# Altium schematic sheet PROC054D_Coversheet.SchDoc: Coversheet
size 558 x 431 mm; Date: Not shown in title block; ApprovedBy: Not shown in title block; CheckedBy: Not shown in title block; Author: Not shown in title block; CompanyName: Not shown in title block; DrawnBy: a0271760; Engineer: Not shown in title block; Organization: Not shown in title block; Address1: Not shown in title block; Address2: Not shown in title block; Address3: Not shown in title block; Address4: Not shown in title block; DocumentNumber: 1; Revision: Use project parameter SCH_Rev; SheetNumber: 1; SheetTotal: 19; PageSetup: Record=PageOptions¦CenterHorizontal=True¦CenterVertical=True¦PrintScale=1.00¦XCorrection=1.00¦YCorrection=1.00¦PrintKind=0¦BorderSize=5000000¦LeftOffset=0¦BottomOffset=0¦Orientation=2¦PaperLength=1000¦PaperWidth=1000¦Scale=100¦PaperSource=15¦PrintQuality=600¦MediaType=1¦DitherType=10¦PaperKind=Letter¦PrintScaleMode=1
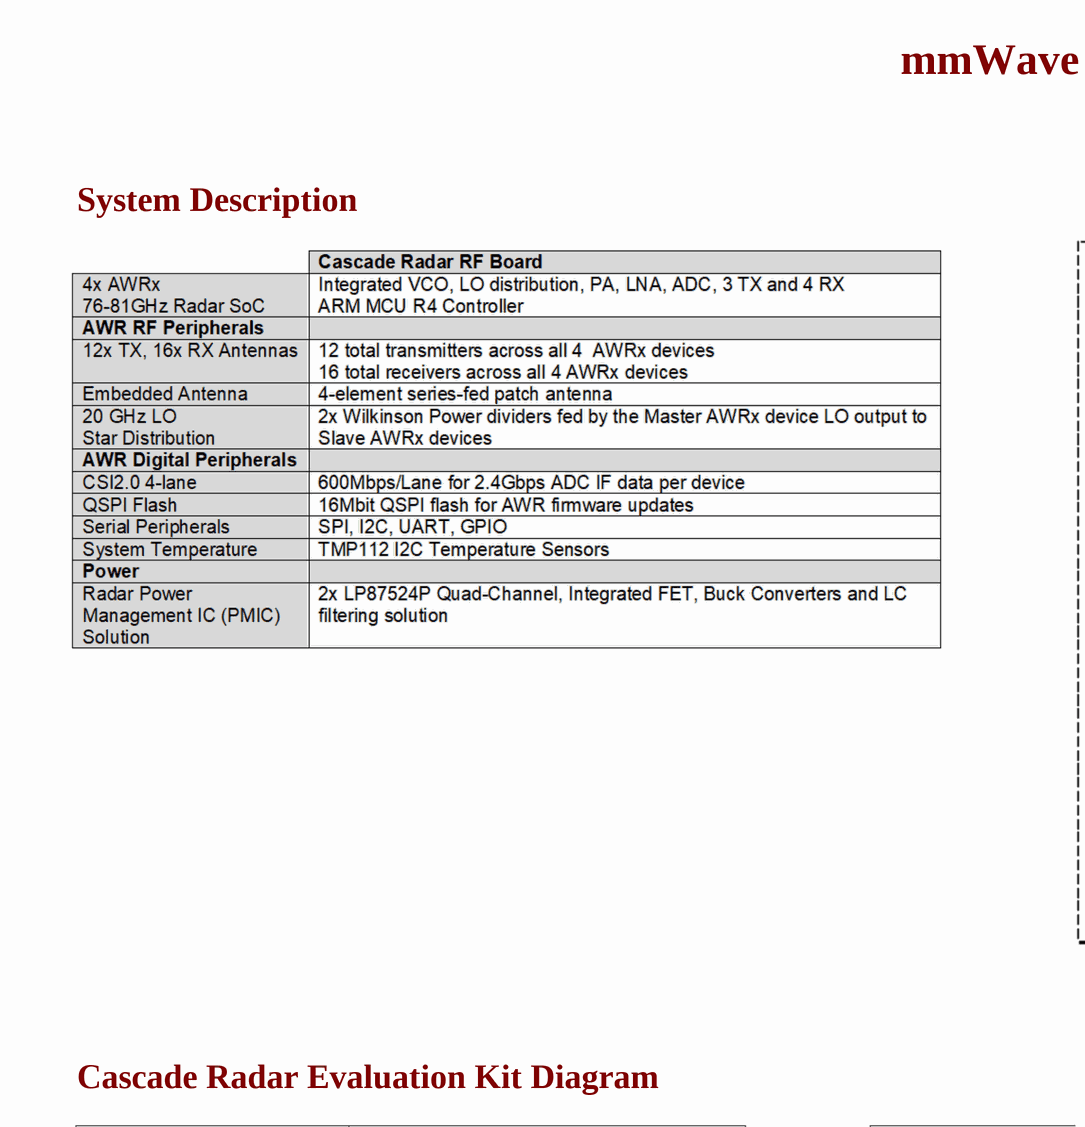
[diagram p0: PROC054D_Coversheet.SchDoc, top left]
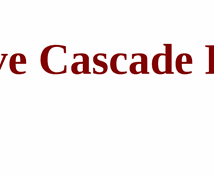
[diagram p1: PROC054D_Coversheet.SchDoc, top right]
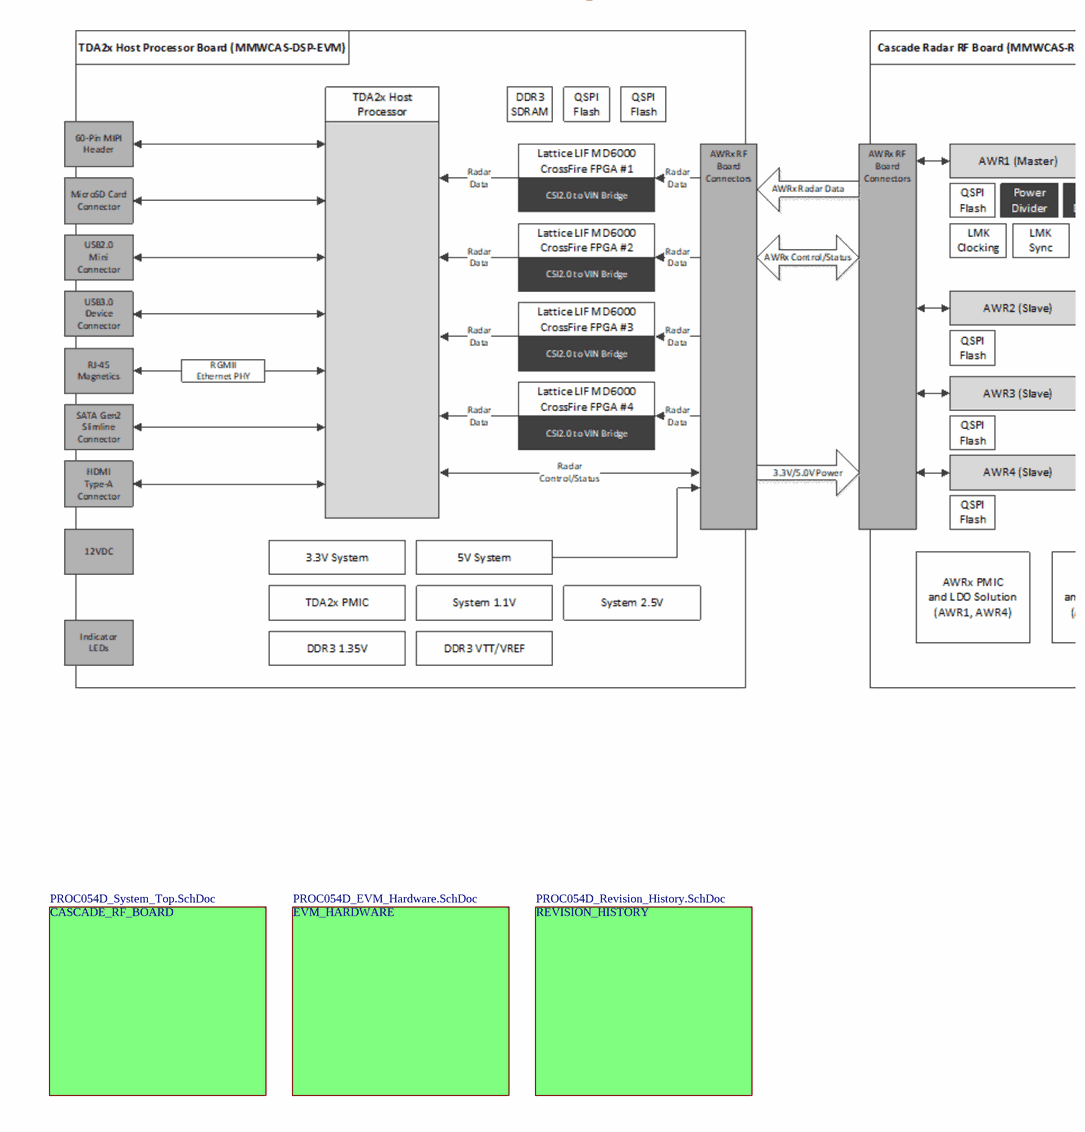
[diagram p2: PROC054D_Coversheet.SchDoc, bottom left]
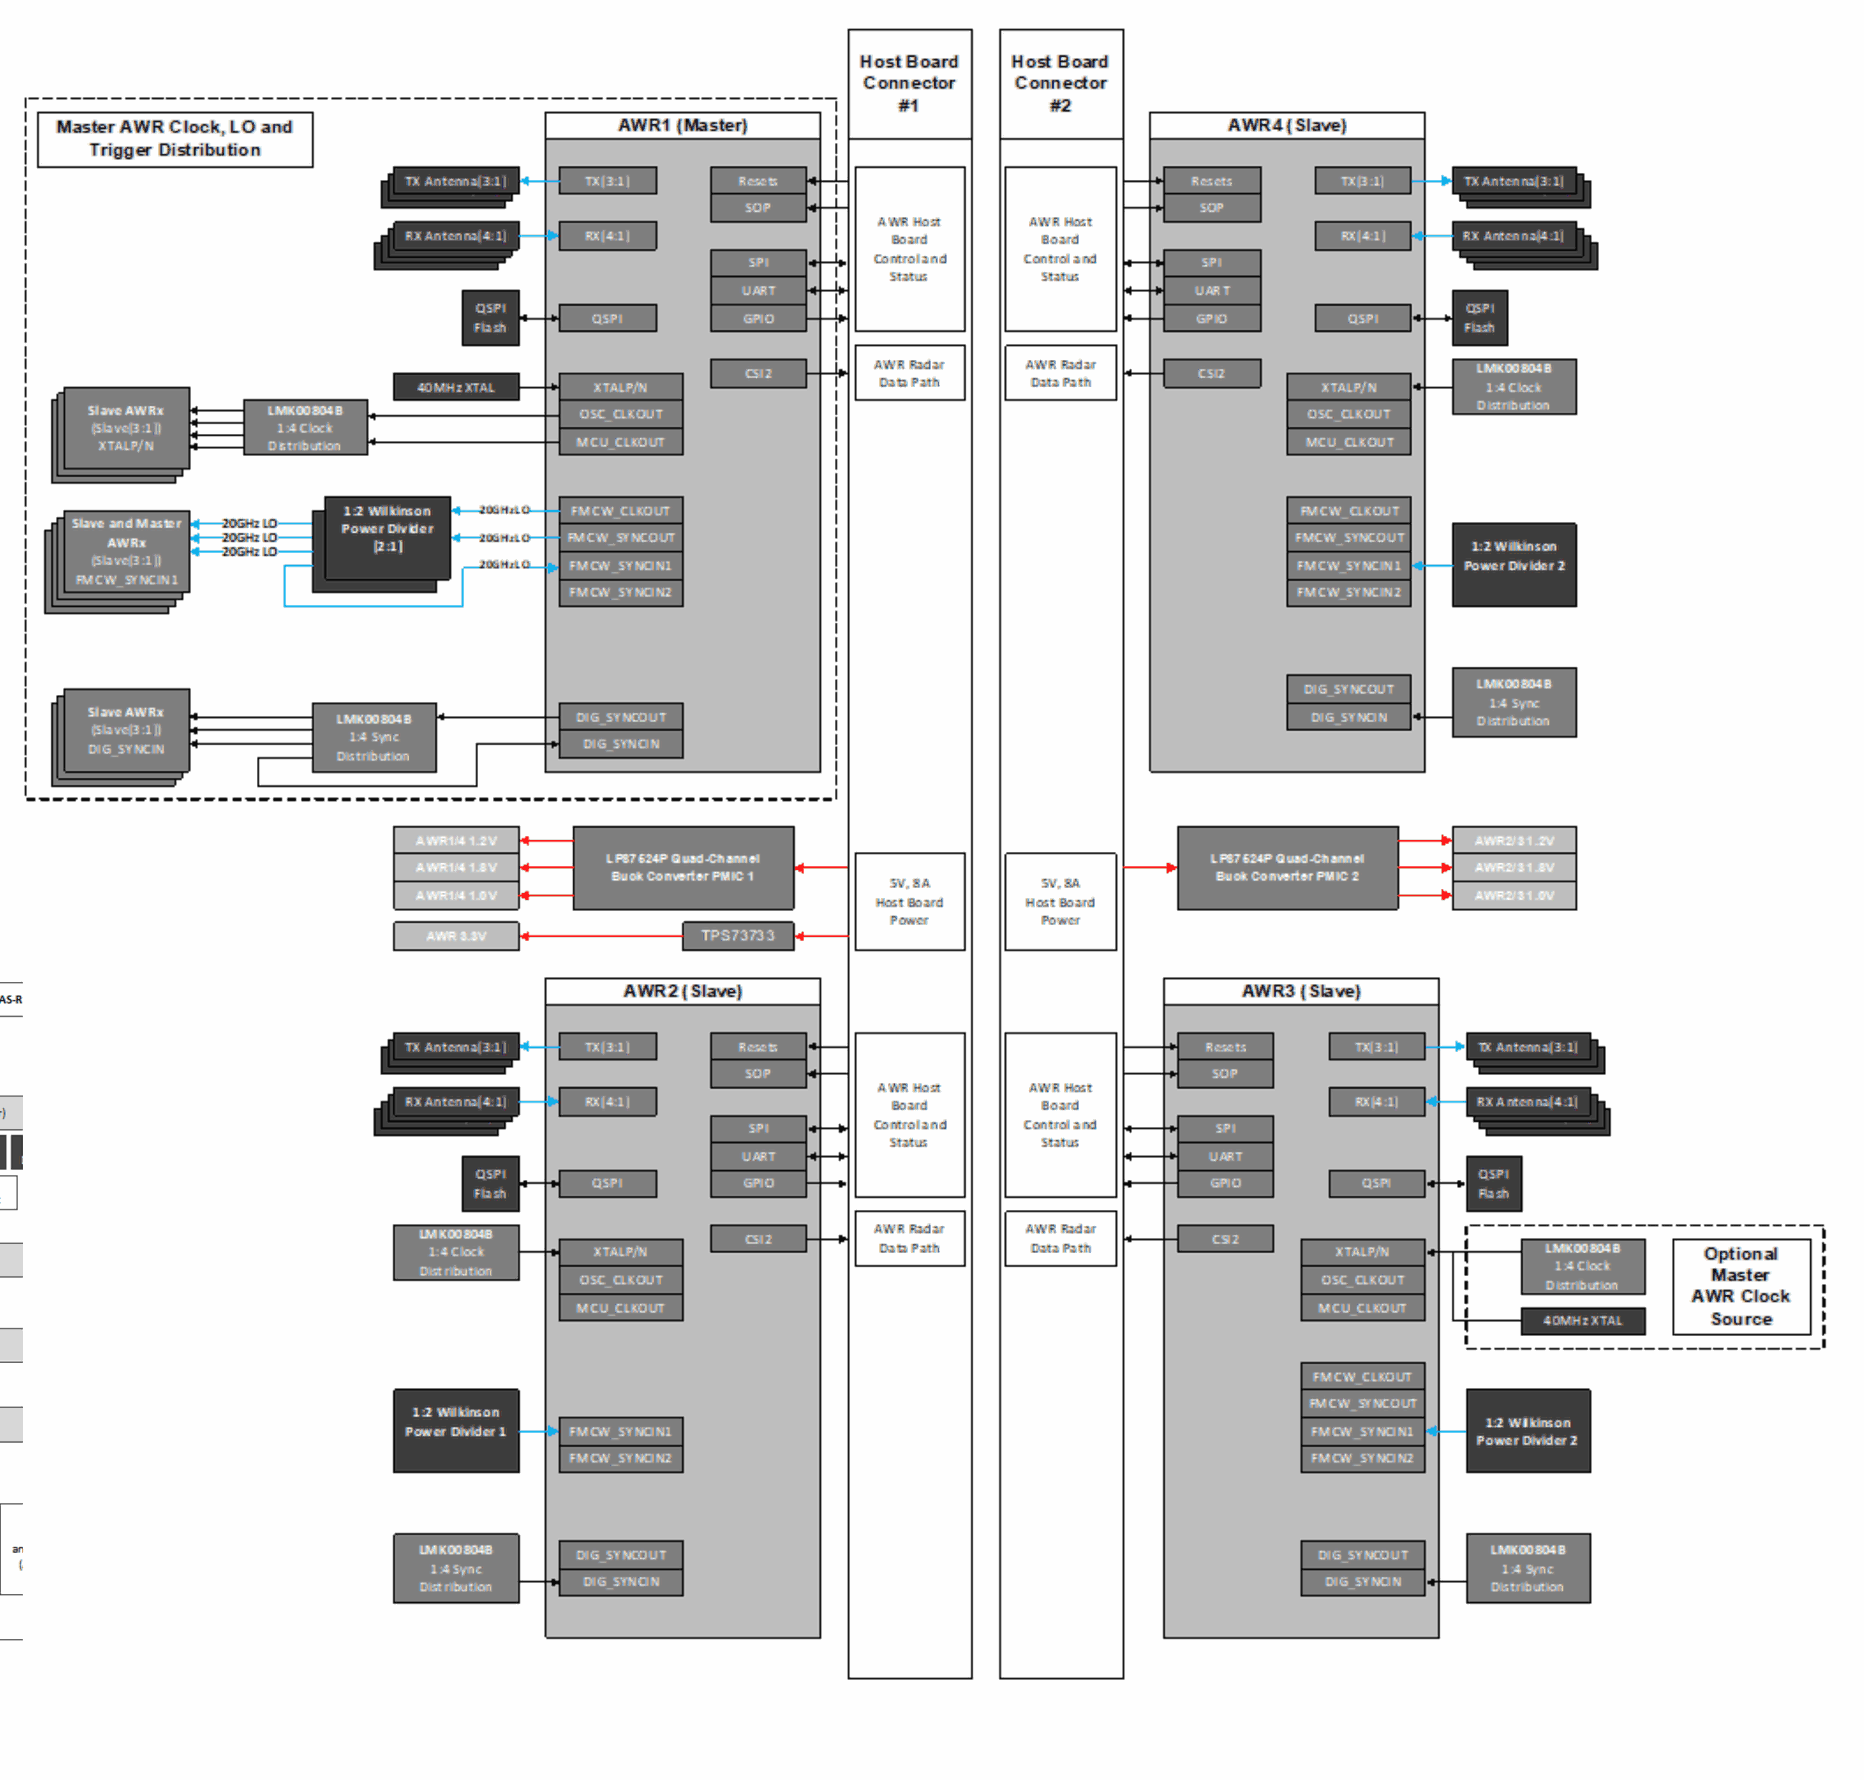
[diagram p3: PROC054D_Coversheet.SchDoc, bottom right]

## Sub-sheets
CASCADE_RF_BOARD = PROC054D_System_Top.SchDoc: no entries
EVM_HARDWARE = PROC054D_EVM_Hardware.SchDoc: no entries
REVISION_HISTORY = PROC054D_Revision_History.SchDoc: no entries

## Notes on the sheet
- mmWave Cascade Radar RF Board (MMWCAS-RF-EVM)
- Cascade Radar RF System Diagram
- System Description
- Cascade Radar Evaluation Kit Diagram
